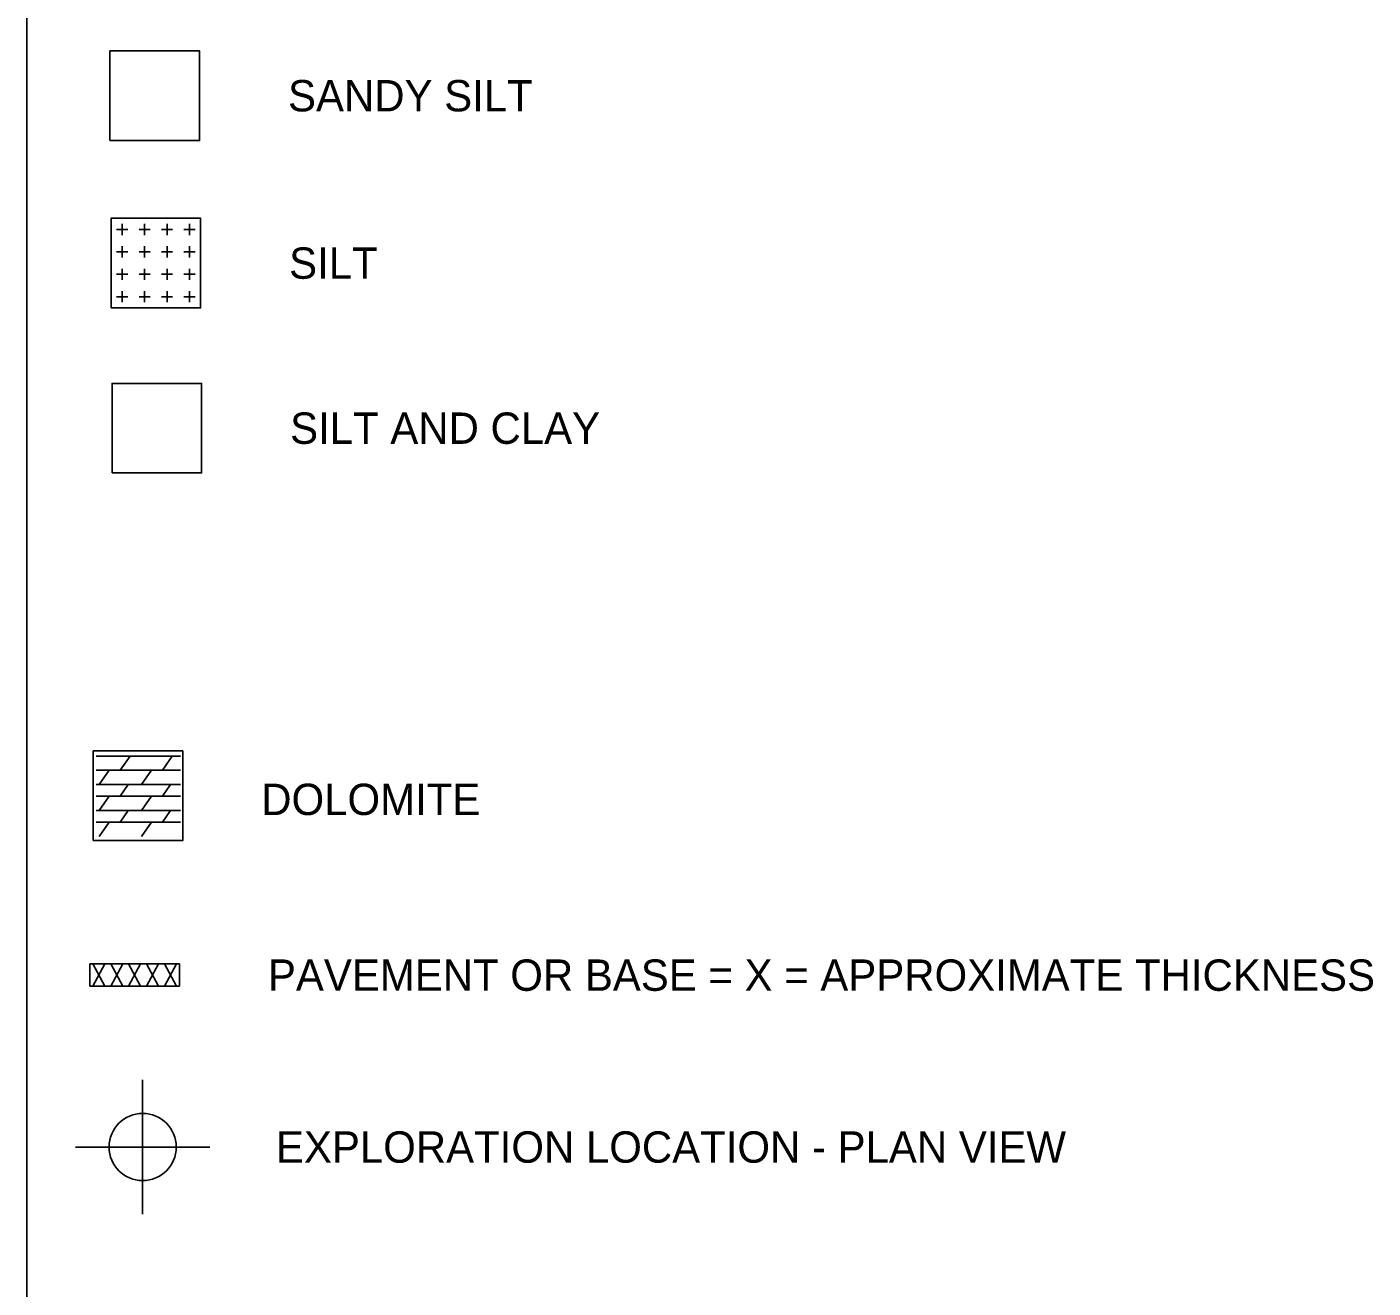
# Model space of a CAD drawing. Extents: x -5.4 to 49.9, y 13.2 to 48.4.
# Drawn here: x 14.42 to 20.42, y 37.72 to 43.35 of the extents above; entities that cross this region are included whole.
import ezdxf

# ---------------------------------------------------------------- set-up
doc = ezdxf.new("R2010")
doc.units = 0
for name, color, linetype in [('GT_Project_Soil_Boring', 7, 'Continuous'), ('GT_Project_Soil_Layers', 7, 'Continuous'), ('SH_Cut_Line', 7, 'Continuous'), ('SH_Data', 7, 'Continuous'), ('SH_Text', 7, 'Continuous')]:
    doc.layers.add(name, color=color, linetype=linetype)

msp = doc.modelspace()

# ---------------------------------------------------------------- linework, layer by layer
at = {"layer": 'GT_Project_Soil_Boring'}
for p, q in [((14.9319, 38.3475), (14.9319, 38.6475)), ((14.9319, 38.4975), (14.9319, 38.3475)), ((14.9319, 38.3475), (14.6319, 38.3475)), ((14.9319, 38.3475), (14.7819, 38.3475)), ((14.9319, 38.3475), (14.9319, 38.0475)), ((14.9319, 38.3475), (15.2319, 38.3475)), ((14.9319, 38.1975), (14.9319, 38.3475)), ((14.9319, 38.3475), (15.0819, 38.3475))]:
    msp.add_line(p, q, dxfattribs=at)
msp.add_circle((14.9319, 38.3475), 0.15, dxfattribs=at)
for start, end in [(90, 180), (270, 360)]:
    msp.add_arc((14.9319, 38.3475), 0.15, start, end, dxfattribs=at)
at = {"layer": 'GT_Project_Soil_Layers'}
for p, q in [((14.7094, 39.1649), (14.7627, 39.065)), ((14.7094, 39.065), (14.7627, 39.1649)), ((14.7894, 39.1649), (14.8427, 39.065)), ((14.7894, 39.065), (14.8427, 39.1649)), ((14.8694, 39.1649), (14.9227, 39.065)), ((14.8694, 39.065), (14.9227, 39.1649)), ((14.9494, 39.1649), (15.0027, 39.065)), ((14.9494, 39.065), (15.0027, 39.1649)), ((15.0294, 39.1649), (15.0827, 39.065)), ((15.0294, 39.065), (15.0827, 39.1649))]:
    msp.add_line(p, q, dxfattribs=at)
at = {"layer": 'SH_Cut_Line'}
for p, q in [((14.7907, 42.4937), (14.7907, 42.4937)), ((15.1907, 42.4937), (15.1907, 42.4937)), ((14.8157, 42.4437), (14.8657, 42.4437)), ((14.8407, 42.4187), (14.8407, 42.4687)), ((14.9157, 42.4437), (14.9657, 42.4437)), ((14.9407, 42.4187), (14.9407, 42.4687)), ((15.0157, 42.4437), (15.0657, 42.4437)), ((15.0407, 42.4187), (15.0407, 42.4687)), ((15.1157, 42.4437), (15.1407, 42.4437)), ((15.1407, 42.4687), (15.1407, 42.4187)), ((15.1407, 42.4437), (15.1657, 42.4437)), ((14.8407, 42.3187), (14.8407, 42.3687)), ((14.9407, 42.3187), (14.9407, 42.3687)), ((15.0407, 42.3187), (15.0407, 42.3687)), ((15.1407, 42.3687), (15.1407, 42.3187)), ((14.8157, 42.3437), (14.8657, 42.3437)), ((14.9157, 42.3437), (14.9657, 42.3437)), ((15.0157, 42.3437), (15.0657, 42.3437)), ((15.1157, 42.3437), (15.1407, 42.3437)), ((15.1407, 42.3437), (15.1657, 42.3437)), ((14.8157, 42.2437), (14.8657, 42.2437)), ((14.8407, 42.2187), (14.8407, 42.2687)), ((14.9157, 42.2437), (14.9657, 42.2437)), ((14.9407, 42.2187), (14.9407, 42.2687)), ((15.0157, 42.2437), (15.0657, 42.2437)), ((15.0407, 42.2187), (15.0407, 42.2687)), ((15.1157, 42.2437), (15.1407, 42.2437)), ((15.1407, 42.2687), (15.1407, 42.2187)), ((15.1407, 42.2437), (15.1657, 42.2437)), ((14.8157, 42.1437), (14.8657, 42.1437)), ((14.8407, 42.1187), (14.8407, 42.1687)), ((14.9157, 42.1437), (14.9657, 42.1437)), ((14.9407, 42.1187), (14.9407, 42.1687)), ((15.0157, 42.1437), (15.0657, 42.1437)), ((15.0407, 42.1187), (15.0407, 42.1687)), ((15.1157, 42.1437), (15.1407, 42.1437)), ((15.1407, 42.1687), (15.1407, 42.1187)), ((15.1407, 42.1437), (15.1657, 42.1437)), ((14.7907, 42.0937), (14.7907, 42.0937)), ((15.1907, 42.0937), (15.1907, 42.0937)), ((14.7239, 40.0924), (15.1007, 40.0924)), ((14.7239, 40.0924), (14.7239, 40.0924)), ((14.8318, 40.0295), (14.8759, 40.0924)), ((15.0202, 40.0295), (15.0643, 40.0924)), ((15.1007, 40.0924), (15.1007, 40.0924)), ((14.7239, 40.0295), (15.1007, 40.0295)), ((14.7376, 39.9652), (14.7826, 40.0295)), ((14.926, 39.9652), (14.971, 40.0295)), ((14.7239, 39.9652), (15.1007, 39.9652)), ((14.8318, 39.9137), (14.8678, 39.9652)), ((15.0202, 39.9137), (15.0562, 39.9652)), ((14.7239, 39.9137), (15.1007, 39.9137)), ((14.7376, 39.8494), (14.7826, 39.9137)), ((14.926, 39.8494), (14.971, 39.9137)), ((14.7239, 39.8494), (15.1007, 39.8494)), ((14.8318, 39.798), (14.8678, 39.8494)), ((15.0202, 39.798), (15.0562, 39.8494)), ((14.7239, 39.798), (15.1007, 39.798)), ((14.7376, 39.7337), (14.7826, 39.798)), ((14.926, 39.7337), (14.971, 39.798)), ((14.7239, 39.7337), (14.7239, 39.7337)), ((15.1007, 39.7337), (15.1007, 39.7337))]:
    msp.add_line(p, q, dxfattribs=at)
at = {"layer": 'SH_Data'}
for p, q in [((14.4153, 29.9123), (14.4153, 47.8483)), ((14.6961, 39.065), (14.6961, 39.1649)), ((14.6961, 39.1649), (15.0961, 39.1649)), ((15.0961, 39.065), (15.0961, 39.1649)), ((14.6961, 39.065), (15.0961, 39.065))]:
    msp.add_line(p, q, dxfattribs=at)
for points in [[(14.7859, 42.8408), (15.1859, 42.8408), (15.1859, 43.2408), (14.7859, 43.2408)], [(14.7907, 42.0937), (15.1907, 42.0937), (15.1907, 42.4937), (14.7907, 42.4937)], [(14.7951, 41.3568), (15.1951, 41.3568), (15.1951, 41.7568), (14.7951, 41.7568)], [(14.711, 39.7159), (15.111, 39.7159), (15.111, 40.1159), (14.711, 40.1159)]]:
    msp.add_lwpolyline(points, close=True, dxfattribs=at)

# ---------------------------------------------------------------- texts
at = {"layer": 'SH_Text'}
for s, p in [('SANDY SILT                                   ', (15.5808, 42.9708)), ('SILT                                         ', (15.5856, 42.2236)), ('SILT AND CLAY                                ', (15.59, 41.4867)), ('DOLOMITE', (15.4613, 39.8297)), ('PAVEMENT OR BASE = X = APPROXIMATE THICKNESS', (15.4911, 39.0449)), ('EXPLORATION LOCATION - PLAN VIEW', (15.5269, 38.2775))]:
    msp.add_text(s, height=0.14, dxfattribs=at).set_placement(p)

doc.saveas('drawing.dxf')
